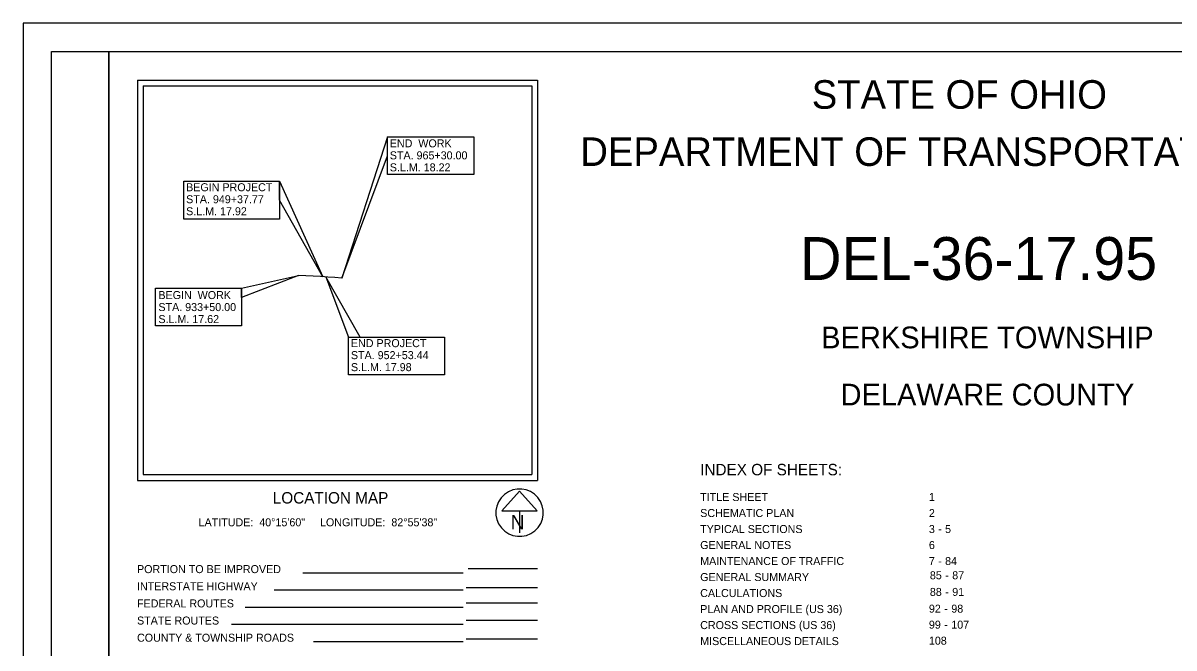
# Model space of a CAD drawing. Extents: x 0 to 34, y 0 to 22.
# Drawn here: x 0 to 20.13, y 11.07 to 22 of the extents above; entities that cross this region are included whole.
import ezdxf

# ---------------------------------------------------------------- set-up
doc = ezdxf.new("R2010")
doc.units = 0
for name, color, linetype in [('GM_X_Adjacent_County', 7, 'Continuous'), ('GM_X_County', 7, 'Continuous'), ('GM_X_Section', 7, 'Continuous'), ('GM_X_Township', 7, 'Continuous')]:
    doc.layers.add(name, color=color, linetype=linetype)

msp = doc.modelspace()

# ---------------------------------------------------------------- linework, layer by layer
at = {"layer": 'GM_X_Adjacent_County'}
for points in [[(5.574, 17.534), (6.377, 19.678), (6.377, 20.008)], [(6.377, 20.008), (7.886, 20.008), (7.886, 19.348), (6.377, 19.348)], [(2.81, 19.231), (4.487, 19.231), (4.487, 18.571), (2.81, 18.571)], [(5.242, 17.561), (4.487, 18.901), (4.487, 19.231)], [(4.817, 17.586), (3.824, 17.198), (3.824, 17.363)], [(5.296, 17.557), (5.692, 16.504), (5.894, 16.504)], [(2.315, 17.363), (3.824, 17.363), (3.824, 16.702), (2.315, 16.702)], [(5.692, 16.504), (7.369, 16.504), (7.369, 15.844), (5.692, 15.844)]]:
    msp.add_lwpolyline(points, close=True, dxfattribs=at)
at = {"layer": 'GM_X_County'}
for points in [[(0.5, 21.5), (1.5, 21.5), (1.5, 0.5), (0.5, 0.5)], [(1.5, 21.5), (33.5, 21.5), (33.5, 0.5), (1.5, 0.5)]]:
    msp.add_lwpolyline(points, close=True, dxfattribs=at)
at = {"layer": 'GM_X_Section'}
msp.add_lwpolyline([(0, 0), (34, 0), (34, 22), (0, 22)], close=True, dxfattribs=at)
at = {"layer": 'GM_X_Township'}
for p, q in [((2, 21), (9, 21)), ((2, 21), (2, 14)), ((9, 21), (9, 14)), ((2.1, 20.9), (2.1, 14.1)), ((2.1, 20.9), (8.9, 20.9)), ((8.9, 20.9), (8.9, 14.1)), ((5.203, 17.564), (4.817, 17.586)), ((5.271, 17.559), (5.203, 17.564)), ((5.332, 17.553), (5.271, 17.559)), ((5.455, 17.546), (5.333, 17.553)), ((5.574, 17.534), (5.455, 17.546)), ((2.1, 14.1), (2.1, 14.1)), ((2.1, 14.1), (8.9, 14.1)), ((2.1, 14.1), (2.1, 14.1)), ((2, 14), (9, 14)), ((8.685, 13.809), (8.377, 13.468)), ((8.992, 13.468), (8.685, 13.809)), ((8.377, 13.468), (8.992, 13.468)), ((8.685, 13.468), (8.685, 13.081)), ((8.685, 13.435), (8.685, 13.435)), ((8.685, 13.435), (8.685, 13.435)), ((7.7, 12.377), (4.894, 12.377)), ((7.783, 12.455), (9, 12.455)), ((9, 12.121), (7.75, 12.121)), ((7.7, 12.077), (4.39, 12.077)), ((7.7, 11.777), (3.885, 11.777)), ((9, 11.849), (7.75, 11.849)), ((7.7, 11.477), (3.645, 11.477)), ((9, 11.549), (7.75, 11.549)), ((7.7, 11.177), (5.078, 11.177)), ((9, 11.222), (7.75, 11.222))]:
    msp.add_line(p, q, dxfattribs=at)
msp.add_arc((8.685, 13.435), 0.415, 129.7798, 129.7633, dxfattribs=at)

# ---------------------------------------------------------------- texts
at = {"layer": 'GM_X_Adjacent_County'}
for s, height, p in [('STATE OF OHIO', 0.5, (13.795, 20.5)), ('END  WORK', 0.14, (6.415, 19.825)), ('DEPARTMENT OF TRANSPORTATION', 0.5, (9.747, 19.5)), ('STA. 965+30.00', 0.14, (6.415, 19.615)), ('S.L.M. 18.22', 0.14, (6.415, 19.405)), ('BEGIN PROJECT', 0.14, (2.853, 19.057)), ('STA. 949+37.77', 0.14, (2.853, 18.847)), ('S.L.M. 17.92', 0.14, (2.853, 18.637)), ('DEL-36-17.95', 0.75, (13.591, 17.505)), ('BEGIN  WORK', 0.14, (2.368, 17.171)), ('STA. 933+50.00', 0.14, (2.368, 16.961)), ('S.L.M. 17.62', 0.14, (2.368, 16.751)), ('BERKSHIRE TOWNSHIP', 0.38, (13.959, 16.31)), ('END PROJECT', 0.14, (5.735, 16.33)), ('STA. 952+53.44', 0.14, (5.735, 16.12)), ('S.L.M. 17.98', 0.14, (5.735, 15.91)), ('DELAWARE COUNTY', 0.38, (14.298, 15.31)), ('INDEX OF SHEETS:', 0.2, (11.844, 14.088)), ('LOCATION MAP', 0.2, (4.369, 13.594)), ('TITLE SHEET', 0.14, (11.844, 13.638)), ('1', 0.14, (15.844, 13.638)), ('SCHEMATIC PLAN', 0.14, (11.844, 13.358)), ('2', 0.14, (15.844, 13.358)), ('LATITUDE:  40°15\'60"     LONGITUDE:  82°55\'38"', 0.14, (3.071, 13.196)), ('TYPICAL SECTIONS', 0.14, (11.844, 13.078)), ('3', 0.14, (15.844, 13.078)), (' - ', 0.14, (15.953, 13.078)), ('5', 0.14, (16.127, 13.078)), ('GENERAL NOTES', 0.14, (11.844, 12.798)), ('6', 0.14, (15.844, 12.798)), ('PORTION TO BE IMPROVED', 0.14, (1.994, 12.377)), ('MAINTENANCE OF TRAFFIC', 0.14, (11.844, 12.518)), ('7', 0.14, (15.844, 12.518)), (' - ', 0.14, (15.953, 12.518)), ('84', 0.14, (16.127, 12.518)), ('GENERAL SUMMARY', 0.14, (11.844, 12.238)), ('85', 0.14, (15.861, 12.269)), (' - ', 0.14, (16.078, 12.269)), ('87', 0.14, (16.252, 12.269)), ('INTERSTATE HIGHWAY', 0.14, (1.994, 12.077)), ('CALCULATIONS', 0.14, (11.844, 11.958)), ('88', 0.14, (15.861, 11.978)), ('91', 0.14, (16.252, 11.978)), ('FEDERAL ROUTES', 0.14, (1.994, 11.777)), (' - ', 0.14, (16.078, 11.978)), ('PLAN AND PROFILE (US 36)', 0.14, (11.844, 11.678)), ('92', 0.14, (15.844, 11.685)), (' - ', 0.14, (16.062, 11.685)), ('98', 0.14, (16.236, 11.685)), ('STATE ROUTES', 0.14, (1.994, 11.477)), ('CROSS SECTIONS (US 36)', 0.14, (11.844, 11.398)), ('99', 0.14, (15.844, 11.405)), ('107', 0.14, (16.236, 11.405)), ('COUNTY & TOWNSHIP ROADS', 0.14, (1.994, 11.177)), (' - ', 0.14, (16.062, 11.405)), ('MISCELLANEOUS DETAILS', 0.14, (11.844, 11.118)), ('108', 0.14, (15.844, 11.125))]:
    msp.add_text(s, height=height, dxfattribs=at).set_placement(p)
at = {"layer": 'GM_X_Township'}
msp.add_text('N', height=0.25, dxfattribs=at).set_placement((8.529, 13.144))

doc.saveas('drawing.dxf')
